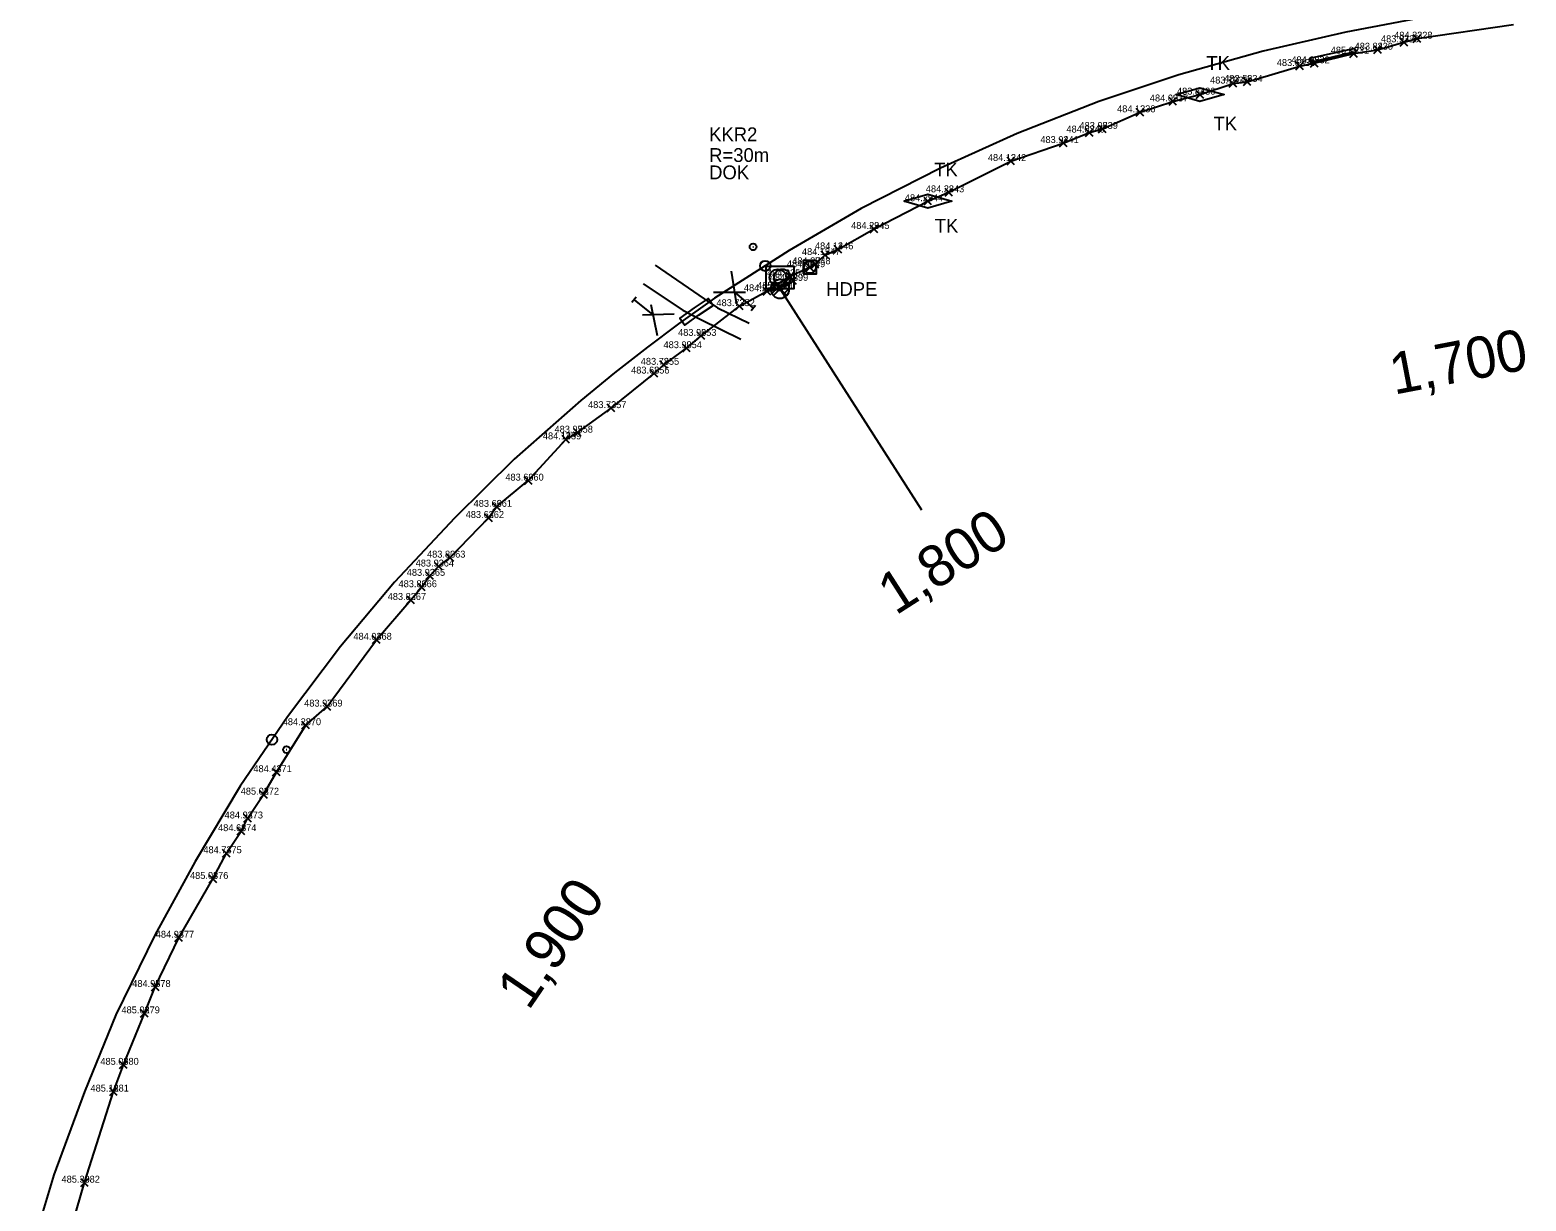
# Model space of a CAD drawing. Extents: x -874058 to -854960, y -10531873 to -1049126.
# Drawn here: x -867731.2 to -867514.3, y -1052277.2 to -1052107.4 of the extents above; entities that cross this region are included whole.
import ezdxf

# ---------------------------------------------------------------- set-up
doc = ezdxf.new("R2010")
doc.units = 0
for name, color, linetype in [('Vrstva 1', 7, 'Continuous'), ('Vrstva 17', 7, 'Continuous'), ('Vrstva 18', 7, 'Continuous'), ('Vrstva 30', 7, 'Continuous'), ('Vrstva 31', 7, 'Continuous'), ('Vrstva 32', 7, 'Continuous'), ('Vrstva 35', 7, 'Continuous'), ('Vrstva 4', 7, 'Continuous'), ('Vrstva 51', 7, 'Continuous'), ('Vrstva 60', 7, 'Continuous'), ('Vrstva 61', 7, 'Continuous'), ('Vrstva 7', 7, 'Continuous')]:
    doc.layers.add(name, color=color, linetype=linetype)

msp = doc.modelspace()

# ---------------------------------------------------------------- linework, layer by layer
at = {"layer": 'Vrstva 1'}
msp.add_lwpolyline([(-867527.97, -1052105.36), (-867540.45, -1052107.75), (-867552.4, -1052110.46), (-867564.62, -1052113.91), (-867576.24, -1052117.78), (-867588.07, -1052122.41), (-867599.19, -1052127.43), (-867610.67, -1052133.31), (-867621.11, -1052139.38), (-867631.92, -1052146.3), (-867637.17, -1052150.02), (-867641.66, -1052153.4), (-867646.46, -1052157.13), (-867651.33, -1052161.14), (-867660.98, -1052169.63), (-867669.6, -1052178.14), (-867678.31, -1052187.47), (-867686.14, -1052196.77), (-867693.83, -1052206.98), (-867700.68, -1052217.01), (-867707.24, -1052227.94), (-867713.08, -1052238.6), (-867718.7, -1052250.15), (-867723.28, -1052261.34), (-867727.71, -1052273.38), (-867731.17, -1052284.97)], dxfattribs=at)
at = {"layer": 'Vrstva 17'}
msp.add_lwpolyline([(-867545.36, -1052112.05), (-867539.29, -1052110.6)], dxfattribs=at)
at = {"layer": 'Vrstva 18'}
msp.add_lwpolyline([(-867539.11, -1052110.08), (-867545.69, -1052111.53), (-867545.55, -1052112.17), (-867538.97, -1052110.74), (-867539.11, -1052110.08)], dxfattribs=at)
at = {"layer": 'Vrstva 30'}
msp.add_lwpolyline([(-867619.08, -1052142.76), (-867617.16, -1052142.76), (-867617.16, -1052140.84), (-867619.08, -1052140.84)], close=True, dxfattribs=at)
msp.add_circle((-867618.12, -1052141.8), 0.864, dxfattribs=at)
at = {"layer": 'Vrstva 31'}
for p, q in [((-867623.79, -1052144.96), (-867623.11, -1052144.28)), ((-867623.62, -1052145.6), (-867622.71, -1052144.68)), ((-867622.21, -1052145.18), (-867621.29, -1052144.25)), ((-867621.49, -1052143.99), (-867621.49, -1052143.99)), ((-867621.49, -1052143.99), (-867621.49, -1052143.99)), ((-867623.41, -1052145.9), (-867623.41, -1052145.9)), ((-867623.41, -1052145.9), (-867623.41, -1052145.9)), ((-867621.81, -1052145.58), (-867621.1, -1052144.87)), ((-867621.48, -1052145.9), (-867621.48, -1052145.9))]:
    msp.add_line(p, q, dxfattribs=at)
for points in [[(-867623.39, -1052143.99), (-867622.45, -1052144.95), (-867623.41, -1052145.9)], [(-867621.49, -1052143.99), (-867622.44, -1052144.95), (-867621.48, -1052145.9)]]:
    msp.add_lwpolyline(points, dxfattribs=at)
for centre, start, end in [((-867622.45, -1052144.95), 134.5239, 224.7609), ((-867622.44, -1052144.95), 45.4761, 134.8422), ((-867622.44, -1052144.95), 315.2391, 45.4761), ((-867622.45, -1052144.95), 224.7623, 315.5517)]:
    msp.add_arc(centre, 1.35, start, end, dxfattribs=at)
at = {"layer": 'Vrstva 32'}
msp.add_line((-867622.51, -1052142.13), (-867622.47, -1052142.14), dxfattribs=at)
for points in [[(-867622.43, -1052144.95), (-867621, -1052143.12), (-867618.12, -1052141.8), (-867617.35, -1052141.37), (-867615.94, -1052140.04), (-867614.05, -1052139.21), (-867608.81, -1052136.25), (-867601.02, -1052132.23), (-867597.98, -1052130.94), (-867588.99, -1052126.41), (-867581.38, -1052123.8), (-867577.6, -1052122.28), (-867575.71, -1052121.75), (-867570.26, -1052119.34), (-867565.51, -1052117.77), (-867561.58, -1052116.78), (-867556.78, -1052115.17), (-867554.73, -1052114.93), (-867547.11, -1052112.64), (-867545, -1052112.24), (-867539.29, -1052110.84), (-867535.83, -1052110.27), (-867532.01, -1052109.19), (-867530.1, -1052108.67), (-867516.12, -1052106.6)], [(-867565.08, -1052116.78), (-867561.58, -1052115.78), (-867558.08, -1052116.78), (-867561.58, -1052117.78), (-867565.08, -1052116.78)], [(-867604.52, -1052132.23), (-867601.02, -1052131.23), (-867597.52, -1052132.23), (-867601.02, -1052133.23), (-867604.52, -1052132.23)], [(-867724.93, -1052280.3), (-867723.26, -1052274.49), (-867719.06, -1052261.29), (-867717.63, -1052257.41), (-867714.57, -1052249.95), (-867713.01, -1052246.13), (-867709.6, -1052238.99), (-867704.64, -1052230.46), (-867702.7, -1052226.74), (-867700.57, -1052223.54), (-867699.62, -1052221.7), (-867697.29, -1052218.25), (-867695.45, -1052214.99), (-867691.2, -1052208.18), (-867688.09, -1052205.48), (-867680.95, -1052195.8), (-867675.98, -1052190.03), (-867674.41, -1052188.18), (-867673.22, -1052186.53), (-867671.93, -1052185.18), (-867670.28, -1052183.89), (-867664.68, -1052178.14), (-867663.53, -1052176.53), (-867658.93, -1052172.73), (-867653.49, -1052166.75), (-867651.8, -1052165.78), (-867646.94, -1052162.22), (-867640.7, -1052157.21), (-867639.3, -1052155.94), (-867636, -1052153.53), (-867633.89, -1052151.75), (-867628.33, -1052147.44), (-867624.35, -1052145.28), (-867621, -1052143.12)], [(-867624.35, -1052145.28), (-867622.43, -1052144.95)]]:
    msp.add_lwpolyline(points, dxfattribs=at)
msp.add_lwpolyline([(-867624.43, -1052141.63), (-867620.44, -1052141.63), (-867620.44, -1052144.95), (-867624.43, -1052144.95)], close=True, dxfattribs=at)
for centre in [(-867622.76, -1052143.3), (-867622.1, -1052143.28)]:
    msp.add_circle(centre, 1.2, dxfattribs=at)
at = {"layer": 'Vrstva 35'}
msp.add_lwpolyline([(-867633.89, -1052151.75), (-867628.33, -1052147.44)], dxfattribs=at)
at = {"layer": 'Vrstva 4'}
for p, q in [((-867628.76, -1052146.94), (-867629.48, -1052142.38)), ((-867643.3, -1052146.13), (-867643.92, -1052146.91)), ((-867643.61, -1052146.52), (-867640.87, -1052148.69)), ((-867632.07, -1052145.43), (-867627.46, -1052145.41)), ((-867626.32, -1052147.7), (-867628.98, -1052145.43)), ((-867637.78, -1052148.58), (-867642.39, -1052148.76)), ((-867641.15, -1052147.19), (-867640.26, -1052151.72)), ((-867626.64, -1052148.08), (-867626, -1052147.32))]:
    msp.add_line(p, q, dxfattribs=at)
at = {"layer": 'Vrstva 51'}
for points in [[(-867640.56, -1052141.49), (-867633.44, -1052146.37), (-867631.52, -1052147.71), (-867626.91, -1052149.89)], [(-867642.29, -1052144.22), (-867636.53, -1052148.02), (-867633.94, -1052149.38), (-867628.14, -1052152.23)], [(-867632.14, -1052147.35), (-867632.85, -1052146.32), (-867634.9, -1052147.71), (-867636.98, -1052149.16), (-867636.24, -1052150.18), (-867634.24, -1052148.75), (-867632.14, -1052147.35)]]:
    msp.add_lwpolyline(points, dxfattribs=at)
at = {"layer": 'Vrstva 60'}
for p, q in [((-867536.38, -1052110.82), (-867535.28, -1052109.72)), ((-867535.28, -1052110.82), (-867536.38, -1052109.72)), ((-867532.56, -1052109.74), (-867531.46, -1052108.64)), ((-867531.46, -1052109.74), (-867532.56, -1052108.64)), ((-867530.65, -1052109.22), (-867529.55, -1052108.12)), ((-867529.55, -1052109.22), (-867530.65, -1052108.12)), ((-867547.66, -1052113.19), (-867546.56, -1052112.09)), ((-867546.56, -1052113.19), (-867547.66, -1052112.09)), ((-867545.55, -1052112.79), (-867544.45, -1052111.69)), ((-867544.45, -1052112.79), (-867545.55, -1052111.69)), ((-867539.84, -1052111.39), (-867538.74, -1052110.29)), ((-867538.74, -1052111.39), (-867539.84, -1052110.29)), ((-867562.13, -1052117.33), (-867561.03, -1052116.23)), ((-867561.03, -1052117.33), (-867562.13, -1052116.23)), ((-867557.33, -1052115.72), (-867556.23, -1052114.62)), ((-867556.23, -1052115.72), (-867557.33, -1052114.62)), ((-867555.28, -1052115.48), (-867554.18, -1052114.38)), ((-867554.18, -1052115.48), (-867555.28, -1052114.38)), ((-867566.06, -1052118.32), (-867564.96, -1052117.22)), ((-867564.96, -1052118.32), (-867566.06, -1052117.22)), ((-867570.81, -1052119.89), (-867569.71, -1052118.79)), ((-867569.71, -1052119.89), (-867570.81, -1052118.79)), ((-867578.15, -1052122.83), (-867577.05, -1052121.73)), ((-867577.05, -1052122.83), (-867578.15, -1052121.73)), ((-867576.26, -1052122.3), (-867575.16, -1052121.2)), ((-867575.16, -1052122.3), (-867576.26, -1052121.2)), ((-867581.93, -1052124.35), (-867580.83, -1052123.25)), ((-867580.83, -1052124.35), (-867581.93, -1052123.25)), ((-867589.54, -1052126.96), (-867588.44, -1052125.86)), ((-867588.44, -1052126.96), (-867589.54, -1052125.86)), ((-867601.57, -1052132.78), (-867600.47, -1052131.68)), ((-867600.47, -1052132.78), (-867601.57, -1052131.68)), ((-867598.53, -1052131.49), (-867597.43, -1052130.39)), ((-867597.43, -1052131.49), (-867598.53, -1052130.39)), ((-867609.36, -1052136.8), (-867608.26, -1052135.7)), ((-867608.26, -1052136.8), (-867609.36, -1052135.7)), ((-867616.49, -1052140.59), (-867615.39, -1052139.49)), ((-867615.39, -1052140.59), (-867616.49, -1052139.49)), ((-867614.6, -1052139.76), (-867613.5, -1052138.66)), ((-867613.5, -1052139.76), (-867614.6, -1052138.66)), ((-867618.67, -1052142.35), (-867617.57, -1052141.25)), ((-867617.57, -1052142.35), (-867618.67, -1052141.25)), ((-867617.9, -1052141.92), (-867616.8, -1052140.82)), ((-867616.8, -1052141.92), (-867617.9, -1052140.82)), ((-867622.98, -1052145.5), (-867621.88, -1052144.4)), ((-867621.88, -1052145.5), (-867622.98, -1052144.4)), ((-867621.55, -1052143.67), (-867620.45, -1052142.57)), ((-867620.45, -1052143.67), (-867621.55, -1052142.57)), ((-867621.14, -1052144.32), (-867620.04, -1052143.22)), ((-867620.04, -1052144.32), (-867621.14, -1052143.22)), ((-867628.88, -1052147.99), (-867627.78, -1052146.89)), ((-867627.78, -1052147.99), (-867628.88, -1052146.89)), ((-867624.9, -1052145.83), (-867623.8, -1052144.73)), ((-867623.8, -1052145.83), (-867624.9, -1052144.73)), ((-867634.44, -1052152.3), (-867633.34, -1052151.2)), ((-867633.34, -1052152.3), (-867634.44, -1052151.2)), ((-867636.55, -1052154.08), (-867635.45, -1052152.98)), ((-867635.45, -1052154.08), (-867636.55, -1052152.98)), ((-867639.85, -1052156.49), (-867638.75, -1052155.39)), ((-867638.75, -1052156.49), (-867639.85, -1052155.39)), ((-867641.25, -1052157.76), (-867640.15, -1052156.66)), ((-867640.15, -1052157.76), (-867641.25, -1052156.66)), ((-867647.49, -1052162.77), (-867646.39, -1052161.67)), ((-867646.39, -1052162.77), (-867647.49, -1052161.67)), ((-867654.04, -1052167.3), (-867652.94, -1052166.2)), ((-867652.94, -1052167.3), (-867654.04, -1052166.2)), ((-867652.35, -1052166.33), (-867651.25, -1052165.23)), ((-867651.25, -1052166.33), (-867652.35, -1052165.23)), ((-867659.48, -1052173.28), (-867658.38, -1052172.18)), ((-867658.38, -1052173.28), (-867659.48, -1052172.18)), ((-867664.08, -1052177.08), (-867662.98, -1052175.98)), ((-867662.98, -1052177.08), (-867664.08, -1052175.98)), ((-867665.23, -1052178.69), (-867664.13, -1052177.59)), ((-867664.13, -1052178.69), (-867665.23, -1052177.59)), ((-867670.83, -1052184.44), (-867669.73, -1052183.34)), ((-867669.73, -1052184.44), (-867670.83, -1052183.34)), ((-867672.48, -1052185.73), (-867671.38, -1052184.63)), ((-867671.38, -1052185.73), (-867672.48, -1052184.63)), ((-867674.96, -1052188.73), (-867673.86, -1052187.63)), ((-867673.86, -1052188.73), (-867674.96, -1052187.63)), ((-867673.77, -1052187.08), (-867672.67, -1052185.98)), ((-867672.67, -1052187.08), (-867673.77, -1052185.98)), ((-867676.53, -1052190.58), (-867675.43, -1052189.48)), ((-867675.43, -1052190.58), (-867676.53, -1052189.48)), ((-867681.5, -1052196.35), (-867680.4, -1052195.25)), ((-867680.4, -1052196.35), (-867681.5, -1052195.25)), ((-867688.64, -1052206.03), (-867687.54, -1052204.93)), ((-867687.54, -1052206.03), (-867688.64, -1052204.93)), ((-867691.75, -1052208.73), (-867690.65, -1052207.63)), ((-867690.65, -1052208.73), (-867691.75, -1052207.63)), ((-867696, -1052215.54), (-867694.9, -1052214.44)), ((-867694.9, -1052215.54), (-867696, -1052214.44)), ((-867697.84, -1052218.8), (-867696.74, -1052217.7)), ((-867696.74, -1052218.8), (-867697.84, -1052217.7)), ((-867700.17, -1052222.25), (-867699.07, -1052221.15)), ((-867699.07, -1052222.25), (-867700.17, -1052221.15)), ((-867701.12, -1052224.09), (-867700.02, -1052222.99)), ((-867700.02, -1052224.09), (-867701.12, -1052222.99)), ((-867703.25, -1052227.29), (-867702.15, -1052226.19)), ((-867702.15, -1052227.29), (-867703.25, -1052226.19)), ((-867705.19, -1052231.01), (-867704.09, -1052229.91)), ((-867704.09, -1052231.01), (-867705.19, -1052229.91)), ((-867710.15, -1052239.54), (-867709.05, -1052238.44)), ((-867709.05, -1052239.54), (-867710.15, -1052238.44)), ((-867713.56, -1052246.68), (-867712.46, -1052245.58)), ((-867712.46, -1052246.68), (-867713.56, -1052245.58)), ((-867715.12, -1052250.5), (-867714.02, -1052249.4)), ((-867714.02, -1052250.5), (-867715.12, -1052249.4)), ((-867718.18, -1052257.96), (-867717.08, -1052256.86)), ((-867717.08, -1052257.96), (-867718.18, -1052256.86)), ((-867719.61, -1052261.84), (-867718.51, -1052260.74)), ((-867718.51, -1052261.84), (-867719.61, -1052260.74)), ((-867723.81, -1052275.04), (-867722.71, -1052273.94)), ((-867722.71, -1052275.04), (-867723.81, -1052273.94))]:
    msp.add_line(p, q, dxfattribs=at)
at = {"layer": 'Vrstva 7'}
for p, q in [((-867626.39, -1052138.85), (-867626.29, -1052138.85)), ((-867601.9, -1052177.03), (-867622.43, -1052144.95)), ((-867694.02, -1052211.73), (-867693.92, -1052211.73))]:
    msp.add_line(p, q, dxfattribs=at)
for centre, radius in [((-867626.34, -1052138.85), 0.5), ((-867624.58, -1052141.6), 0.75), ((-867696.09, -1052210.28), 0.75), ((-867693.97, -1052211.73), 0.5)]:
    msp.add_circle(centre, radius, dxfattribs=at)

# ---------------------------------------------------------------- texts
at = {"layer": 'Vrstva 32'}
for s, p in [('TK', (-867560.65, -1052113.19)), ('TK', (-867559.6, -1052121.98)), ('KKR2', (-867632.72, -1052123.53)), ('R=30m', (-867632.72, -1052126.54)), ('DOK', (-867632.72, -1052129.05)), ('TK', (-867600.09, -1052128.64)), ('TK', (-867600.02, -1052136.79)), ('HDPE', (-867615.76, -1052145.96))]:
    msp.add_text(s, height=2, dxfattribs=at).set_placement(p)
at = {"layer": 'Vrstva 60'}
for s, p in [('328', (-867530.1, -1052108.67)), ('331', (-867539.29, -1052110.84)), ('330', (-867535.83, -1052110.27)), ('329', (-867532.01, -1052109.19)), ('333', (-867547.11, -1052112.64)), ('332', (-867545, -1052112.24)), ('335', (-867556.78, -1052115.17)), ('334', (-867554.73, -1052114.93)), ('336', (-867561.58, -1052116.78)), ('338', (-867570.26, -1052119.34)), ('337', (-867565.51, -1052117.77)), ('339', (-867575.71, -1052121.75)), ('341', (-867581.38, -1052123.8)), ('340', (-867577.6, -1052122.28)), ('342', (-867588.99, -1052126.41)), ('344', (-867601.02, -1052132.23)), ('343', (-867597.98, -1052130.94)), ('345', (-867608.81, -1052136.25)), ('346', (-867614.05, -1052139.21)), ('348', (-867617.35, -1052141.37)), ('347', (-867615.94, -1052140.04)), ('350', (-867621, -1052143.12)), ('349', (-867618.12, -1052141.8)), ('351', (-867624.35, -1052145.28)), ('400', (-867622.43, -1052144.95)), ('399', (-867620.59, -1052143.77)), ('352', (-867628.33, -1052147.44)), ('353', (-867633.89, -1052151.75)), ('354', (-867636, -1052153.53)), ('355', (-867639.3, -1052155.94)), ('356', (-867640.7, -1052157.21)), ('357', (-867646.94, -1052162.22)), ('359', (-867653.49, -1052166.75)), ('358', (-867651.8, -1052165.78)), ('360', (-867658.93, -1052172.73)), ('362', (-867664.68, -1052178.14)), ('361', (-867663.53, -1052176.53)), ('363', (-867670.28, -1052183.89)), ('365', (-867673.22, -1052186.53)), ('364', (-867671.93, -1052185.18)), ('366', (-867674.41, -1052188.18)), ('367', (-867675.98, -1052190.03)), ('368', (-867680.95, -1052195.8)), ('369', (-867688.09, -1052205.48)), ('370', (-867691.2, -1052208.18)), ('371', (-867695.45, -1052214.99)), ('372', (-867697.29, -1052218.25)), ('374', (-867700.57, -1052223.54)), ('373', (-867699.62, -1052221.7)), ('375', (-867702.7, -1052226.74)), ('376', (-867704.64, -1052230.46)), ('377', (-867709.6, -1052238.99)), ('378', (-867713.01, -1052246.13)), ('379', (-867714.57, -1052249.95)), ('380', (-867717.63, -1052257.41)), ('381', (-867719.06, -1052261.29)), ('382', (-867723.26, -1052274.49))]:
    msp.add_text(s, height=1, dxfattribs=at).set_placement(p)
at = {"layer": 'Vrstva 61'}
for s, p in [('484.32 ', (-867533.43, -1052108.67)), ('485.02 ', (-867542.62, -1052110.84)), ('483.84 ', (-867539.16, -1052110.27)), ('483.97 ', (-867535.34, -1052109.19)), ('483.63 ', (-867550.44, -1052112.64)), ('484.35 ', (-867548.33, -1052112.24)), ('483.79 ', (-867560.11, -1052115.17)), ('483.56 ', (-867558.06, -1052114.93)), ('483.84 ', (-867564.91, -1052116.78)), ('484.12 ', (-867573.59, -1052119.34)), ('484.09 ', (-867568.84, -1052117.77)), ('483.95 ', (-867579.04, -1052121.75)), ('483.94 ', (-867584.71, -1052123.8)), ('484.03 ', (-867580.93, -1052122.28)), ('484.13 ', (-867592.32, -1052126.41)), ('484.29 ', (-867604.35, -1052132.23)), ('484.28 ', (-867601.31, -1052130.94)), ('484.29 ', (-867612.14, -1052136.25)), ('484.14 ', (-867617.38, -1052139.21)), ('484.27 ', (-867620.68, -1052141.37)), ('484.15 ', (-867619.27, -1052140.04)), ('484.23 ', (-867624.33, -1052143.12)), ('484.30 ', (-867621.45, -1052141.8)), ('484.27 ', (-867627.68, -1052145.28)), ('485.38 ', (-867625.76, -1052144.95)), ('484.23 ', (-867623.92, -1052143.77)), ('483.72 ', (-867631.66, -1052147.44)), ('483.96 ', (-867637.22, -1052151.75)), ('483.90 ', (-867639.33, -1052153.53)), ('483.78 ', (-867642.63, -1052155.94)), ('483.68 ', (-867644.03, -1052157.21)), ('483.73 ', (-867650.27, -1052162.22)), ('484.14 ', (-867656.82, -1052166.75)), ('483.95 ', (-867655.13, -1052165.78)), ('483.60 ', (-867662.26, -1052172.73)), ('483.62 ', (-867668.01, -1052178.14)), ('483.66 ', (-867666.86, -1052176.53)), ('483.80 ', (-867673.61, -1052183.89)), ('483.93 ', (-867676.55, -1052186.53)), ('483.93 ', (-867675.26, -1052185.18)), ('483.86 ', (-867677.74, -1052188.18)), ('483.82 ', (-867679.31, -1052190.03)), ('484.04 ', (-867684.28, -1052195.8)), ('483.97 ', (-867691.42, -1052205.48)), ('484.28 ', (-867694.53, -1052208.18)), ('484.43 ', (-867698.78, -1052214.99)), ('485.02 ', (-867700.62, -1052218.25)), ('484.68 ', (-867703.9, -1052223.54)), ('484.92 ', (-867702.95, -1052221.7)), ('484.74 ', (-867706.03, -1052226.74)), ('485.03 ', (-867707.97, -1052230.46)), ('484.93 ', (-867712.93, -1052238.99)), ('484.95 ', (-867716.34, -1052246.13)), ('485.02 ', (-867717.9, -1052249.95)), ('485.05 ', (-867720.96, -1052257.41)), ('485.12 ', (-867722.39, -1052261.29)), ('485.39 ', (-867726.59, -1052274.49))]:
    msp.add_text(s, height=1, dxfattribs=at).set_placement(p)
at = {"layer": 'Vrstva 7'}
for s, rotation, p in [('1,700', 10.841, (-867533.44, -1052160.29)), ('1,800', 32.6252, (-867605.68, -1052192.34)), ('1,900', 55.6683, (-867658.9, -1052249.67))]:
    msp.add_text(s, height=6, rotation=rotation, dxfattribs=at).set_placement(p)

doc.saveas('drawing.dxf')
